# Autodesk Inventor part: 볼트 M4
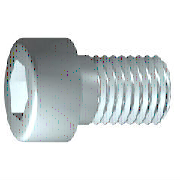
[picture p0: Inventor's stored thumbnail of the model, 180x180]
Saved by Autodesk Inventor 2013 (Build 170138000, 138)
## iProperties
IsCustomPart: 0
Created: 2012-02
Part Number: 볼트 M4
Material: 스테인리스강
Description: 6각 소켓 머리 캡 나사
Document SubType Name: Modeling
Standard: ISO 4762
Designer: mduedu
Standard Revision: Fourth edition 2004-03-01
Standards Organization: ISO
Language: ko-KR
Size Designation: M4 x 12
Categories: <MemberInstance><Categories><Category DisplayName="조임쇠" InternalName="e4da775c-781d-43d5-af7c-5136215cf5a6" Mnemonic="FSTN"><Category DisplayName="볼트" InternalN
Density: 8.08 g/cm^3
Mass: 2.29719 g
Surface Area: 3.30853 cm^2
Volume: 0.284306 cm^3
Author: mduedu
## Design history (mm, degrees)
sketch "스케치1"
  geometry: L1 (-1, 0)-(10, 0); L2 (10, 0)-(10, 2); L3 (10, 2)-(1.75, 2); L4 (1.75, 2)-(1.32, 2); L5 (1.32, 2)-(0, 2); L6 (0, 2)-(0, 3.5); L7 (0, 3.5)-(-4, 3.5); L8 (-4, 3.5)-(-4, 1.732); L9 (-4, 1.732)-(-2, 1.732); L10 (-2, 1.732)-(-1, 0); L11 (-7.2, 0)-(15.2, 0) reference; L12 (0, -0.7)-(0, 4.2) reference; L13 (1.75, 2)-(0, 2)
  constraints: 22 end point, 6 parallel, 2 collinear, 2 perpendicular, 1 horizontal, 1 point on line
  dimensions: "d1" = 8.25 distance from line of L3.end L2 (= GEL); "d2" = 0.42952 distance of L4.end L3.end (computed from GAL); "d3" = 4 distance between parallel lines of L8 L6 (= KOH); "d4" = 2 distance of L8.end L9.end (= INTI); "d5" = 60 deg angle of L10 L1; "d6" = 4 diameter of L3 L1 (= GD); "d7" = 4 diameter of L5 L1 (= BDM); "d8" = 3.4641 diameter of L9 L1 (= 1.1547 x SW); "d9" = 7 diameter of L7 L1 (= KOD); "d26" = 10 distance between parallel lines of L12 L2 (= NLG)
revolve "본체" sketch "스케치1" stored, may be unused: angle "d10" = 90 deg
sketch "스케치2"
  geometry: L1 (0, -4.9)-(0, 4.9) reference; L2 (-4.9, 0)-(4.9, 0) reference; L3 (1.732, 0)-(0.866, -1.5); L4 (0.866, -1.5)-(-0.866, -1.5); L5 (-0.866, -1.5)-(-1.732, 0); L6 (-1.732, 0)-(-0.866, 1.5); L7 (-0.866, 1.5)-(0.866, 1.5); L8 (0.866, 1.5)-(1.732, 0); 2 further points
  constraints: 12 end point, 1 coincident, 1 horizontal alignment, 1 point on line, 12 other
extrude "슬롯" join sketch "스케치2" stored distance "d11" = 10; taper "d12" = 0 deg
workplane "Work Plane1"
fillet "Fillet2" dims "d30" = 0.1 (= R)
body "Solid1"
fillet "모깎기1" dims "d17" = 0.4 (= RR)
feature "스레드" dims "d13" = 8.25 (= GEL), "d14" = 0
chamfer "모따기1" distance "d15" = 0.42941 (= -0.5 x SPD + 0.5 x GD); stored, may be unused: second distance "d16" = 0.42941 (= GUL), angle "d27" = 45 deg
other parameters: "GD" = 4 [user parameter; used in 2 equation terms], "NLG" = 10 [user parameter; used in 1 equation term], "GEL" = 8.25 [user parameter; used in 2 equation terms], "KOD" = 7 [user parameter; used in 1 equation term], "KOH" = 4 [user parameter; used in 1 equation term], "INTI" = 2 [user parameter; used in 1 equation term], "GAL" = 0.42941 (= 0.61345 x PTC) [user parameter; used in 1 equation term], "GUL" = 0.42941 (= 0.61345 x PTC) [user parameter; used in 1 equation term], "BDM" = 4 (= NND) [user parameter; used in 1 equation term], "SW" = 3 [user parameter; used in 2 equation terms], "RR" = 0.4 [user parameter; used in 1 equation term], "SPD" = 3.14117 (= NND - 1.2269 x PTC) [user parameter; used in 1 equation term], "d19" = 0, "d28" = 0, "d29" = 0, "R" = 0.1 [user parameter; used in 1 equation term], "TOA" = 30 deg [user parameter], "GD1" = 3.14117 (= THREADDIA - 1.2269 x PTC) [user parameter], "THREADDIA" = 4 [user parameter; used in 1 equation term], "FAWI" = 45 deg [user parameter], "TPU" = 14.28571 (computed from PTC) [user parameter], "PTC" = 0.7 [user parameter; used in 5 equation terms], "NND" = 4 [user parameter; used in 2 equation terms], "E0" = 3.465 (= 1.155 x SW) [user parameter]
